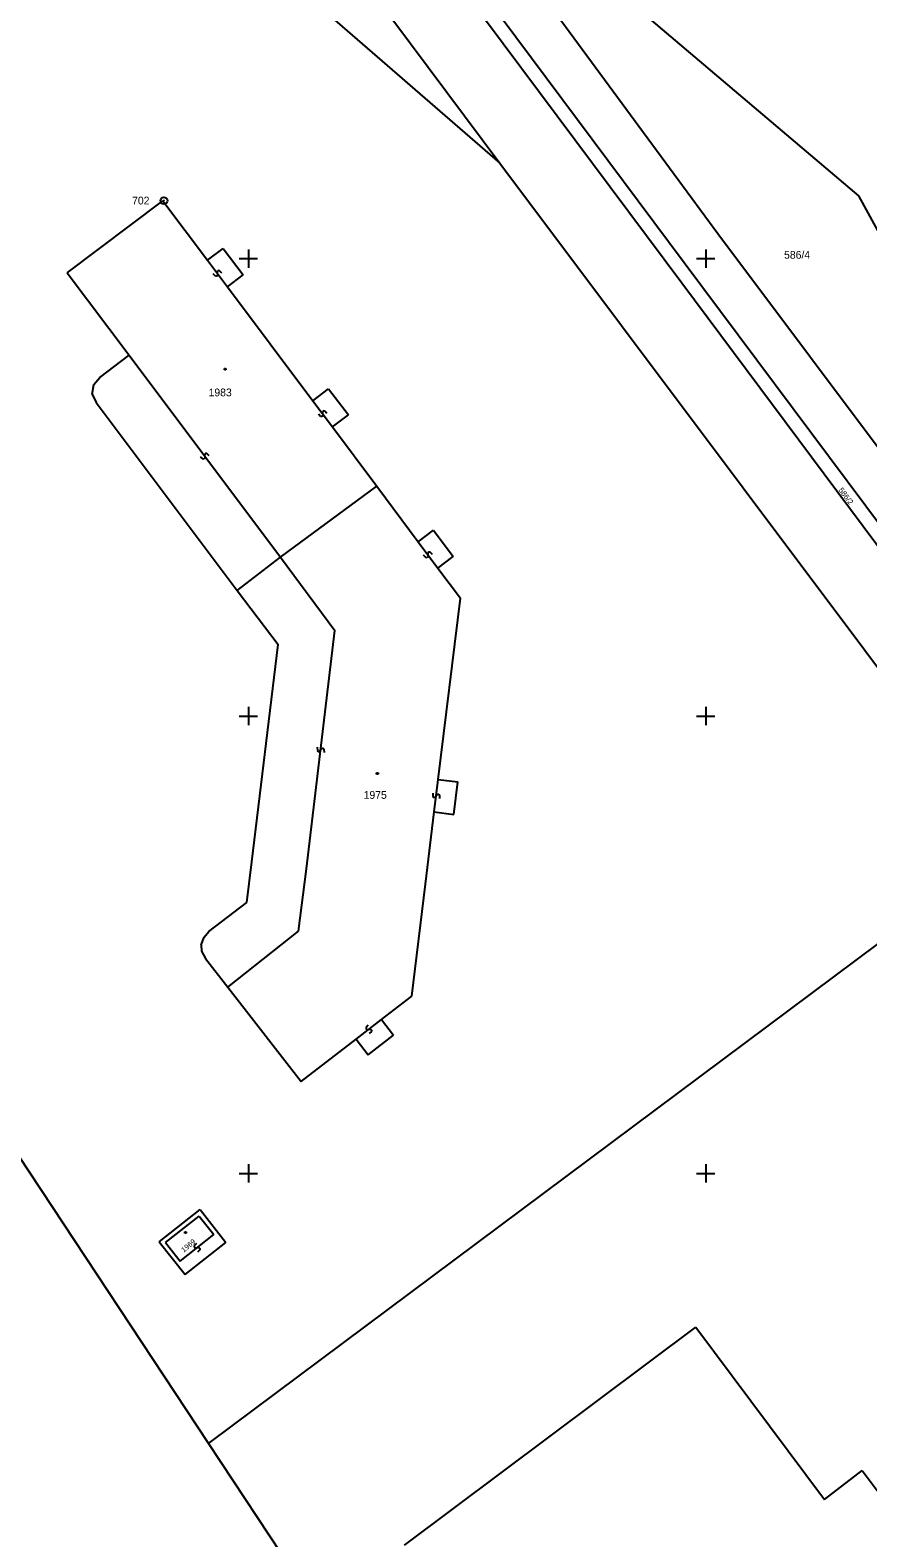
# Model space of a CAD drawing. Extents: x -493648 to -493033, y -1127718 to -1127026.
# Drawn here: x -493273.9 to -493182.3, y -1127439.8 to -1127275 of the extents above; entities that cross this region are included whole.
import ezdxf

# ---------------------------------------------------------------- set-up
doc = ezdxf.new("R2010")
doc.units = 0
doc.layers.add('katastrální mapa', color=7, linetype='Continuous')
doc.layers.add('síť', color=7, linetype='Continuous')

msp = doc.modelspace()

# ---------------------------------------------------------------- linework, layer by layer
at = {"layer": 'katastrální mapa'}
for p, q in [((-493300.83, -1127221.6), (-493222.53, -1127289.56)), ((-493240.14, -1127252.38), (-493202.62, -1127302.64)), ((-493231.53, -1127252.6), (-493198.67, -1127297.24)), ((-493228.76, -1127254.59), (-493183.29, -1127293.12)), ((-493247.64, -1127255.9), (-493222.53, -1127289.56)), ((-493235.98, -1127255.31), (-493202.36, -1127300.42)), ((-493222.53, -1127289.56), (-493182.62, -1127342.8)), ((-493183.29, -1127293.12), (-493159.33, -1127337.18)), ((-493269.81, -1127301.55), (-493259.34, -1127293.68)), ((-493259.34, -1127293.68), (-493254.48, -1127300.16)), ((-493198.67, -1127297.24), (-493150.83, -1127361.25)), ((-493254.48, -1127300.16), (-493252.76, -1127298.88)), ((-493252.76, -1127298.88), (-493250.58, -1127301.78)), ((-493254.48, -1127300.16), (-493252.3, -1127303.07)), ((-493253.39, -1127301.36), (-493253.41, -1127301.5)), ((-493253.31, -1127301.31), (-493253.39, -1127301.36)), ((-493253.17, -1127301.33), (-493253.31, -1127301.31)), ((-493252.92, -1127301.58), (-493253.17, -1127301.33)), ((-493202.36, -1127300.42), (-493160.5, -1127356.56)), ((-493269.81, -1127301.55), (-493263.04, -1127310.57)), ((-493253.61, -1127301.9), (-493253.86, -1127301.65)), ((-493253.47, -1127301.92), (-493253.61, -1127301.9)), ((-493253.39, -1127301.86), (-493253.47, -1127301.92)), ((-493253.41, -1127301.5), (-493253.37, -1127301.73)), ((-493253.37, -1127301.73), (-493253.39, -1127301.86)), ((-493252.3, -1127303.07), (-493250.58, -1127301.78)), ((-493252.3, -1127303.07), (-493242.95, -1127315.54)), ((-493202.62, -1127302.64), (-493173.25, -1127342.08)), ((-493266.25, -1127313.01), (-493263.04, -1127310.57)), ((-493263.04, -1127310.57), (-493246.49, -1127332.65)), ((-493252.6, -1127312.01), (-493252.45, -1127312.01)), ((-493252.6, -1127312.16), (-493252.6, -1127312.01)), ((-493252.45, -1127312.16), (-493252.6, -1127312.16)), ((-493252.45, -1127312.01), (-493252.45, -1127312.16)), ((-493267.07, -1127314.82), (-493266.9, -1127313.77)), ((-493266.9, -1127313.77), (-493266.25, -1127313.01)), ((-493242.95, -1127315.54), (-493241.23, -1127314.25)), ((-493241.23, -1127314.25), (-493239.07, -1127317.08)), ((-493267.07, -1127314.82), (-493266.64, -1127315.74)), ((-493266.64, -1127315.74), (-493251.24, -1127336.27)), ((-493242.95, -1127315.54), (-493240.82, -1127318.38)), ((-493242.1, -1127317.25), (-493242.35, -1127317)), ((-493241.96, -1127317.27), (-493242.1, -1127317.25)), ((-493241.88, -1127317.21), (-493241.96, -1127317.27)), ((-493241.88, -1127316.71), (-493241.9, -1127316.85)), ((-493241.9, -1127316.85), (-493241.86, -1127317.07)), ((-493241.8, -1127316.65), (-493241.88, -1127316.71)), ((-493241.86, -1127317.07), (-493241.88, -1127317.21)), ((-493241.66, -1127316.67), (-493241.8, -1127316.65)), ((-493241.41, -1127316.92), (-493241.66, -1127316.67)), ((-493240.82, -1127318.38), (-493239.07, -1127317.08)), ((-493240.82, -1127318.38), (-493235.96, -1127324.86)), ((-493254.99, -1127321.9), (-493255.24, -1127321.65)), ((-493254.85, -1127321.92), (-493254.99, -1127321.9)), ((-493254.77, -1127321.86), (-493254.85, -1127321.92)), ((-493254.76, -1127321.36), (-493254.78, -1127321.5)), ((-493254.78, -1127321.5), (-493254.75, -1127321.72)), ((-493254.75, -1127321.72), (-493254.77, -1127321.86)), ((-493254.68, -1127321.3), (-493254.76, -1127321.36)), ((-493254.54, -1127321.32), (-493254.68, -1127321.3)), ((-493254.29, -1127321.57), (-493254.54, -1127321.32)), ((-493246.49, -1127332.65), (-493235.96, -1127324.86)), ((-493235.96, -1127324.86), (-493231.44, -1127330.95)), ((-493231.44, -1127330.95), (-493229.76, -1127329.7)), ((-493231.44, -1127330.95), (-493229.29, -1127333.82)), ((-493229.76, -1127329.7), (-493227.62, -1127332.57)), ((-493251.24, -1127336.27), (-493246.49, -1127332.65)), ((-493246.49, -1127332.65), (-493240.55, -1127340.66)), ((-493230.59, -1127332.67), (-493230.84, -1127332.42)), ((-493230.45, -1127332.69), (-493230.59, -1127332.67)), ((-493230.37, -1127332.63), (-493230.45, -1127332.69)), ((-493230.36, -1127332.13), (-493230.38, -1127332.27)), ((-493230.38, -1127332.27), (-493230.35, -1127332.5)), ((-493230.35, -1127332.5), (-493230.37, -1127332.63)), ((-493230.28, -1127332.08), (-493230.36, -1127332.13)), ((-493230.14, -1127332.1), (-493230.28, -1127332.08)), ((-493229.89, -1127332.35), (-493230.14, -1127332.1)), ((-493229.29, -1127333.82), (-493227.62, -1127332.57)), ((-493229.29, -1127333.82), (-493226.83, -1127337.11)), ((-493251.24, -1127336.27), (-493246.76, -1127342.19)), ((-493229.26, -1127356.94), (-493226.83, -1127337.11)), ((-493243.65, -1127366.72), (-493240.55, -1127340.66)), ((-493249.64, -1127365.95), (-493246.76, -1127342.19)), ((-493182.62, -1127342.8), (-493166.74, -1127364.1)), ((-493242.47, -1127353.39), (-493242.46, -1127353.75)), ((-493242.46, -1127353.75), (-493242.37, -1127353.86)), ((-493242.37, -1127353.86), (-493242.27, -1127353.87)), ((-493242.27, -1127353.87), (-493242.16, -1127353.78)), ((-493242.16, -1127353.78), (-493242.04, -1127353.6)), ((-493242.04, -1127353.6), (-493241.93, -1127353.51)), ((-493241.93, -1127353.51), (-493241.83, -1127353.52)), ((-493241.83, -1127353.52), (-493241.74, -1127353.63)), ((-493241.74, -1127353.63), (-493241.73, -1127353.99)), ((-493235.98, -1127356.2), (-493235.83, -1127356.2)), ((-493235.98, -1127356.35), (-493235.98, -1127356.2)), ((-493235.83, -1127356.35), (-493235.98, -1127356.35)), ((-493235.83, -1127356.2), (-493235.83, -1127356.35)), ((-493229.69, -1127360.49), (-493229.26, -1127356.94)), ((-493229.26, -1127356.94), (-493227.12, -1127357.2)), ((-493227.56, -1127360.75), (-493227.12, -1127357.2)), ((-493229.84, -1127358.42), (-493229.83, -1127358.77)), ((-493229.83, -1127358.77), (-493229.75, -1127358.88)), ((-493229.75, -1127358.88), (-493229.65, -1127358.9)), ((-493229.65, -1127358.9), (-493229.54, -1127358.81)), ((-493229.54, -1127358.81), (-493229.41, -1127358.62)), ((-493229.41, -1127358.62), (-493229.3, -1127358.53)), ((-493229.3, -1127358.53), (-493229.2, -1127358.55)), ((-493229.2, -1127358.55), (-493229.12, -1127358.66)), ((-493229.12, -1127358.66), (-493229.11, -1127359.01)), ((-493230.65, -1127368.38), (-493229.69, -1127360.49)), ((-493229.69, -1127360.49), (-493227.56, -1127360.75)), ((-493250.18, -1127370.4), (-493249.64, -1127365.95)), ((-493244.51, -1127373.53), (-493243.65, -1127366.72)), ((-493232.13, -1127380.62), (-493230.65, -1127368.38)), ((-493254.31, -1127373.56), (-493250.18, -1127370.4)), ((-493254.36, -1127429.53), (-493177.2, -1127371.91)), ((-493254.82, -1127374.18), (-493254.31, -1127373.56)), ((-493252.23, -1127379.63), (-493244.51, -1127373.53)), ((-493255.16, -1127375), (-493254.82, -1127374.18)), ((-493255.16, -1127375), (-493255.11, -1127375.71)), ((-493255.11, -1127375.71), (-493254.69, -1127376.49)), ((-493254.69, -1127376.49), (-493252.23, -1127379.63)), ((-493252.23, -1127379.63), (-493244.23, -1127389.95)), ((-493235.46, -1127383.18), (-493232.13, -1127380.62)), ((-493238.23, -1127385.33), (-493235.46, -1127383.18)), ((-493236.89, -1127383.79), (-493237.14, -1127384.04)), ((-493235.46, -1127383.18), (-493234.15, -1127384.88)), ((-493244.23, -1127389.95), (-493238.23, -1127385.33)), ((-493238.23, -1127385.33), (-493236.92, -1127387.02)), ((-493237.14, -1127384.04), (-493237.16, -1127384.18)), ((-493237.16, -1127384.18), (-493237.09, -1127384.26)), ((-493237.09, -1127384.26), (-493236.95, -1127384.28)), ((-493236.95, -1127384.28), (-493236.74, -1127384.23)), ((-493236.92, -1127387.02), (-493234.15, -1127384.88)), ((-493236.55, -1127384.47), (-493236.8, -1127384.72)), ((-493236.74, -1127384.23), (-493236.6, -1127384.25)), ((-493236.6, -1127384.25), (-493236.53, -1127384.33)), ((-493236.53, -1127384.33), (-493236.55, -1127384.47)), ((-493282.75, -1127386.56), (-493254.36, -1127429.53)), ((-493259.75, -1127407.46), (-493255.28, -1127403.94)), ((-493259.07, -1127407.55), (-493255.39, -1127404.66)), ((-493255.39, -1127404.66), (-493253.76, -1127406.67)), ((-493255.28, -1127403.94), (-493252.46, -1127407.56)), ((-493257.47, -1127409.59), (-493253.76, -1127406.67)), ((-493256.95, -1127406.39), (-493256.8, -1127406.39)), ((-493256.95, -1127406.54), (-493256.95, -1127406.39)), ((-493256.8, -1127406.54), (-493256.95, -1127406.54)), ((-493256.8, -1127406.39), (-493256.8, -1127406.54)), ((-493259.75, -1127407.46), (-493256.91, -1127411.04)), ((-493259.07, -1127407.55), (-493257.47, -1127409.59)), ((-493256.91, -1127411.04), (-493252.46, -1127407.56)), ((-493255.91, -1127407.92), (-493255.93, -1127408.06)), ((-493255.93, -1127408.06), (-493255.86, -1127408.14)), ((-493255.67, -1127407.66), (-493255.91, -1127407.92)), ((-493255.86, -1127408.14), (-493255.72, -1127408.15)), ((-493255.72, -1127408.15), (-493255.51, -1127408.11)), ((-493255.32, -1127408.34), (-493255.56, -1127408.6)), ((-493255.51, -1127408.11), (-493255.37, -1127408.12)), ((-493255.37, -1127408.12), (-493255.3, -1127408.2)), ((-493255.3, -1127408.2), (-493255.32, -1127408.34)), ((-493232.95, -1127440.62), (-493201.08, -1127416.82)), ((-493201.08, -1127416.82), (-493187.04, -1127435.66)), ((-493254.36, -1127429.53), (-493226.07, -1127472.34)), ((-493187.04, -1127435.66), (-493182.89, -1127432.48)), ((-493182.89, -1127432.48), (-493156.39, -1127468.02))]:
    msp.add_line(p, q, dxfattribs=at)
for radius in [0.375, 0.005]:
    msp.add_circle((-493259.23, -1127293.66), radius, dxfattribs=at)
at = {"layer": 'síť'}
for p, q in [((-493250, -1127299), (-493250, -1127301)), ((-493200, -1127299), (-493200, -1127301)), ((-493251, -1127300), (-493249, -1127300)), ((-493201, -1127300), (-493199, -1127300)), ((-493250, -1127349), (-493250, -1127351)), ((-493200, -1127349), (-493200, -1127351)), ((-493251, -1127350), (-493249, -1127350)), ((-493201, -1127350), (-493199, -1127350)), ((-493251, -1127400), (-493249, -1127400)), ((-493250, -1127399), (-493250, -1127401)), ((-493201, -1127400), (-493199, -1127400)), ((-493200, -1127399), (-493200, -1127401))]:
    msp.add_line(p, q, dxfattribs=at)

# ---------------------------------------------------------------- texts
at = {"layer": 'katastrální mapa'}
for s, p in [('702', (-493262.71, -1127294.08)), ('586/4', (-493191.44, -1127300.01)), ('1983', (-493254.35, -1127315.05)), ('1975', (-493237.4, -1127359.05))]:
    msp.add_text(s, height=0.849996, dxfattribs=at).set_placement(p)
for s, height, rotation, p in [('586/2', 0.599994, 307.161, (-493185.54, -1127325.31)), ('1969', 0.569994, 39.5381694, (-493257.06, -1127408.67))]:
    msp.add_text(s, height=height, rotation=rotation, dxfattribs=at).set_placement(p)

doc.saveas('drawing.dxf')
